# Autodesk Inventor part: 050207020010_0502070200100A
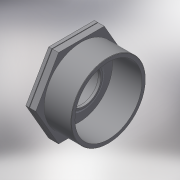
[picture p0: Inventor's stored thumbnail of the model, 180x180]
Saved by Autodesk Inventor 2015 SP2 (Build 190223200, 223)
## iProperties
Created: 2017-05
Part Number: 050207020010_0502070200100A
Material: Generic
Description: PLASSON REDUCING BUSHING 2"-1"
Document SubType Name: Modeling
Designer: KIM
Density: 1 g/cm^3
Appearance: Default
Author: KIM
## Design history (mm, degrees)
derived "050207.ipt"
feature "Solid1::050207.ipt"
tag "TaggingFeature1"
body "Solid1"
other parameters: "d1" = 59.614, "d2" = 63, "d5" = 26, "d8" = 0.41, "d12" = 0, "d15" = 41, "d19" = 0, "d30" = 9.11111, "d31" = 4.55556, "d33" = 30.291, "d34" = 53.6526, "d36" = 3.15, "d37" = 36.3492, "d38" = 27.06, "d39" = 27.2619, "d40" = 2.6, "d41" = 0, "H_" = 41, "R_" = 59.614, "E_" = 63, "l_2" = 26, "Rp_" = 30.291
